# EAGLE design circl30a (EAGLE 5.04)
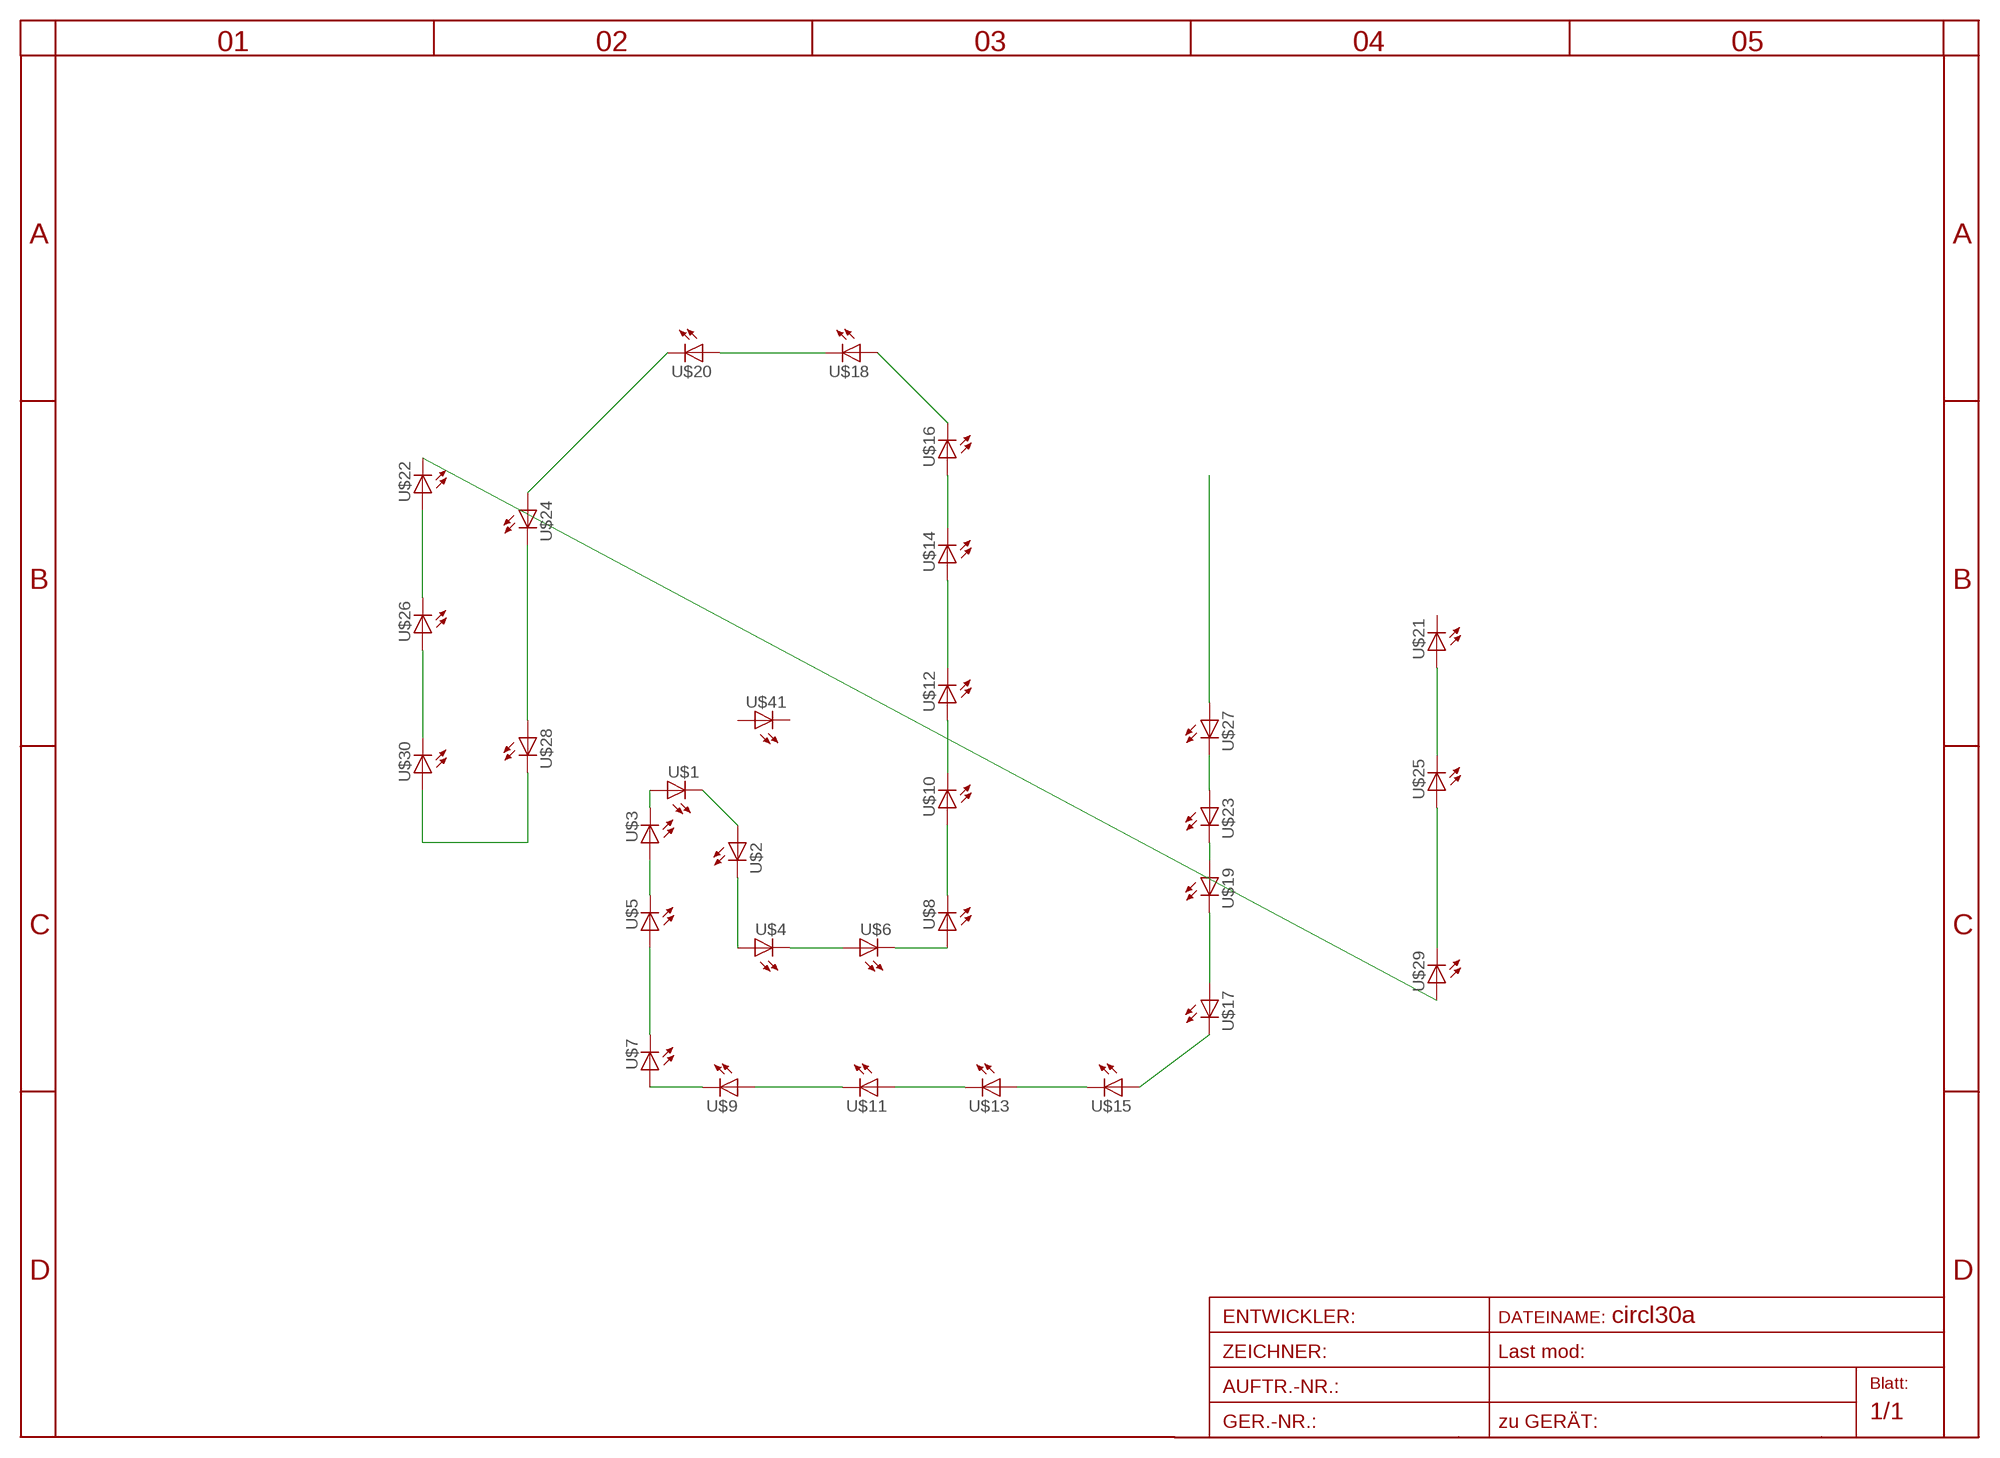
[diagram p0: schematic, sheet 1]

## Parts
U$1  LED5MM  [LED5MM]
U$2  LED5MM  [LED5MM]
U$3  LED5MM  [LED5MM]
U$4  LED5MM  [LED5MM]
U$5  LED5MM  [LED5MM]
U$6  LED5MM  [LED5MM]
U$7  LED5MM  [LED5MM]
U$8  LED5MM  [LED5MM]
U$9  LED5MM  [LED5MM]
U$10  LED5MM  [LED5MM]
U$11  LED5MM  [LED5MM]
U$12  LED5MM  [LED5MM]
U$13  LED5MM  [LED5MM]
U$14  LED5MM  [LED5MM]
U$15  LED5MM  [LED5MM]
U$16  LED5MM  [LED5MM]
U$17  LED5MM  [LED5MM]
U$18  LED5MM  [LED5MM]
U$19  LED5MM  [LED5MM]
U$20  LED5MM  [LED5MM]
U$21  LED5MM  [LED5MM]
U$22  LED5MM  [LED5MM]
U$23  LED5MM  [LED5MM]
U$24  LED5MM  [LED5MM]
U$25  LED5MM  [LED5MM]
U$26  LED5MM  [LED5MM]
U$27  LED5MM  [LED5MM]
U$28  LED5MM  [LED5MM]
U$29  LED5MM  [LED5MM]
U$30  LED5MM  [LED5MM]
U$41  LED5MM  [LED5MM]

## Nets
N$1: U$10.K(C) U$12.A
N$2: U$22.K(C) U$29.A
N$3: U$27.A
N$4: U$20.K(C) U$24.A
N$5: U$24.K(C) U$28.A
N$6: U$12.K(C) U$14.A
N$7: U$14.K(C) U$16.A
N$8: U$16.K(C) U$18.A
N$9: U$18.K(C) U$20.A
N$10: U$22.A U$26.K(C)
N$11: U$8.K(C) U$10.A
N$12: U$6.K(C) U$8.A
N$13: U$4.K(C) U$6.A
N$14: U$2.K(C) U$4.A
N$15: U$1.K(C) U$2.A
N$16: U$1.A U$3.K(C)
N$17: U$3.A U$5.K(C)
N$18: U$5.A U$7.K(C)
N$19: U$7.A U$9.K(C)
N$20: U$9.A U$11.K(C)
N$21: U$11.A U$13.K(C)
N$22: U$13.A U$15.K(C)
N$23: U$15.A U$17.K(C)
N$24: U$17.A U$19.K(C)
N$25: U$25.A U$29.K(C)
N$26: U$21.A U$25.K(C)
N$27: U$26.A U$30.K(C)
N$28: U$23.A U$27.K(C)
N$29: U$19.A U$23.K(C)
N$30: U$28.K(C) U$30.A
Unconnected: U$21.K(C) U$41.A U$41.K(C)

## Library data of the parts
U$1-U$30 U$41 = led(2):LED: LED

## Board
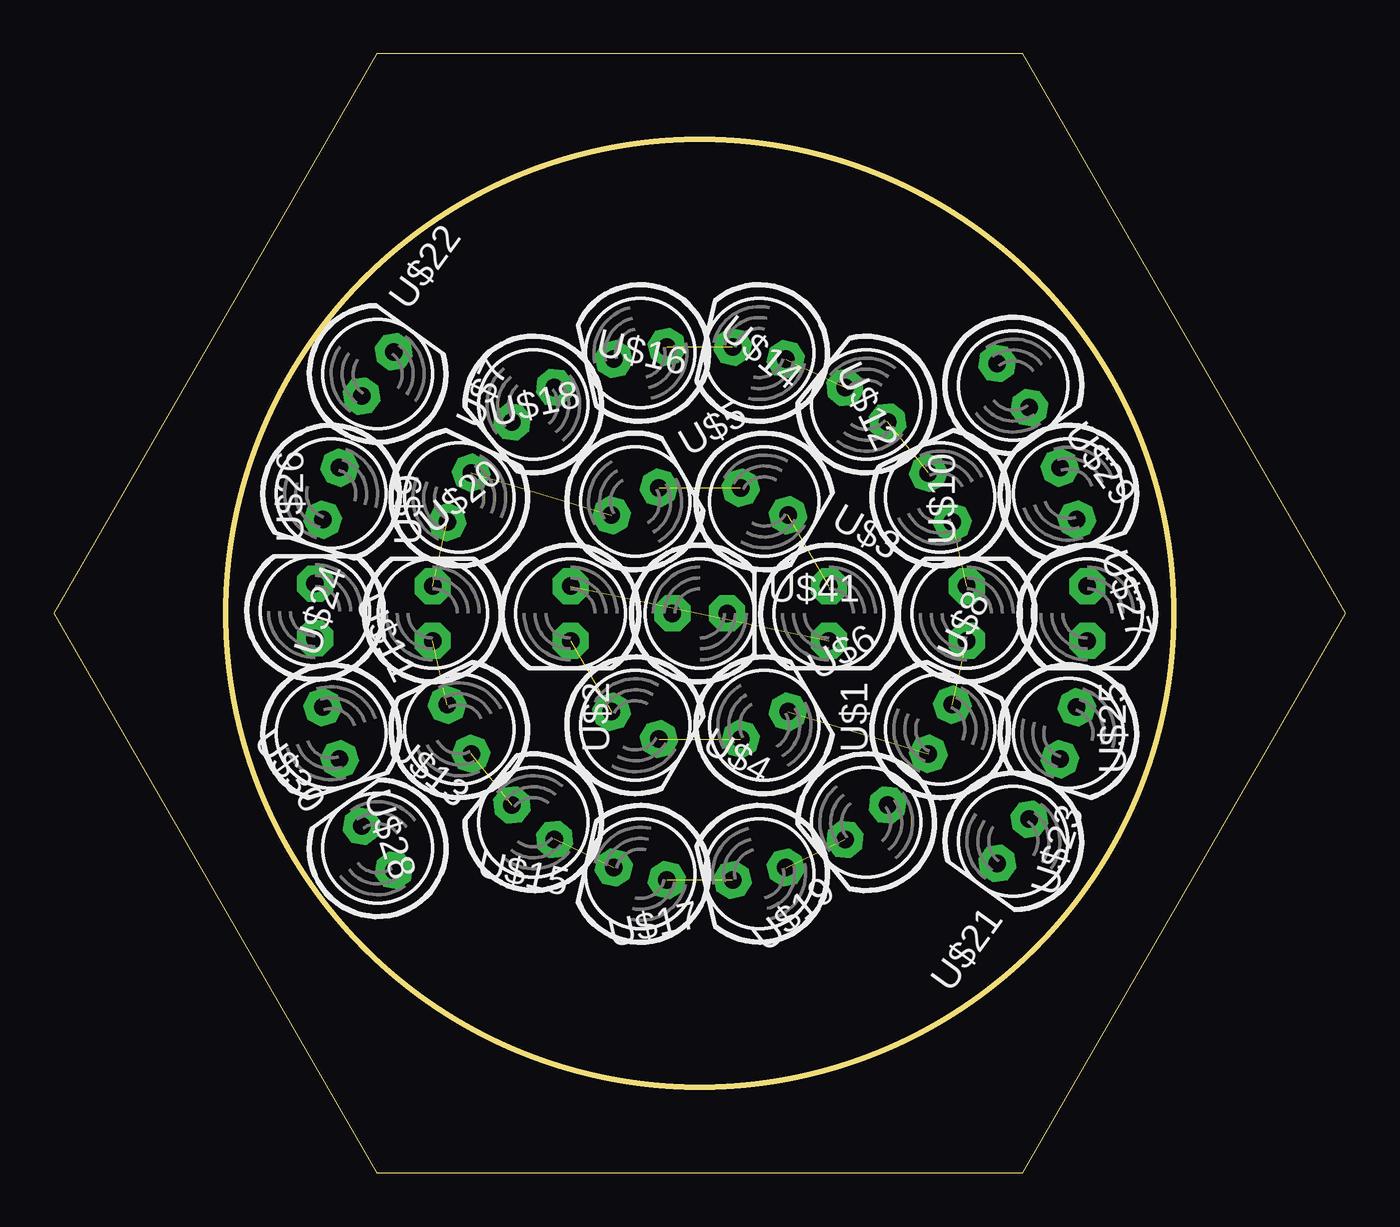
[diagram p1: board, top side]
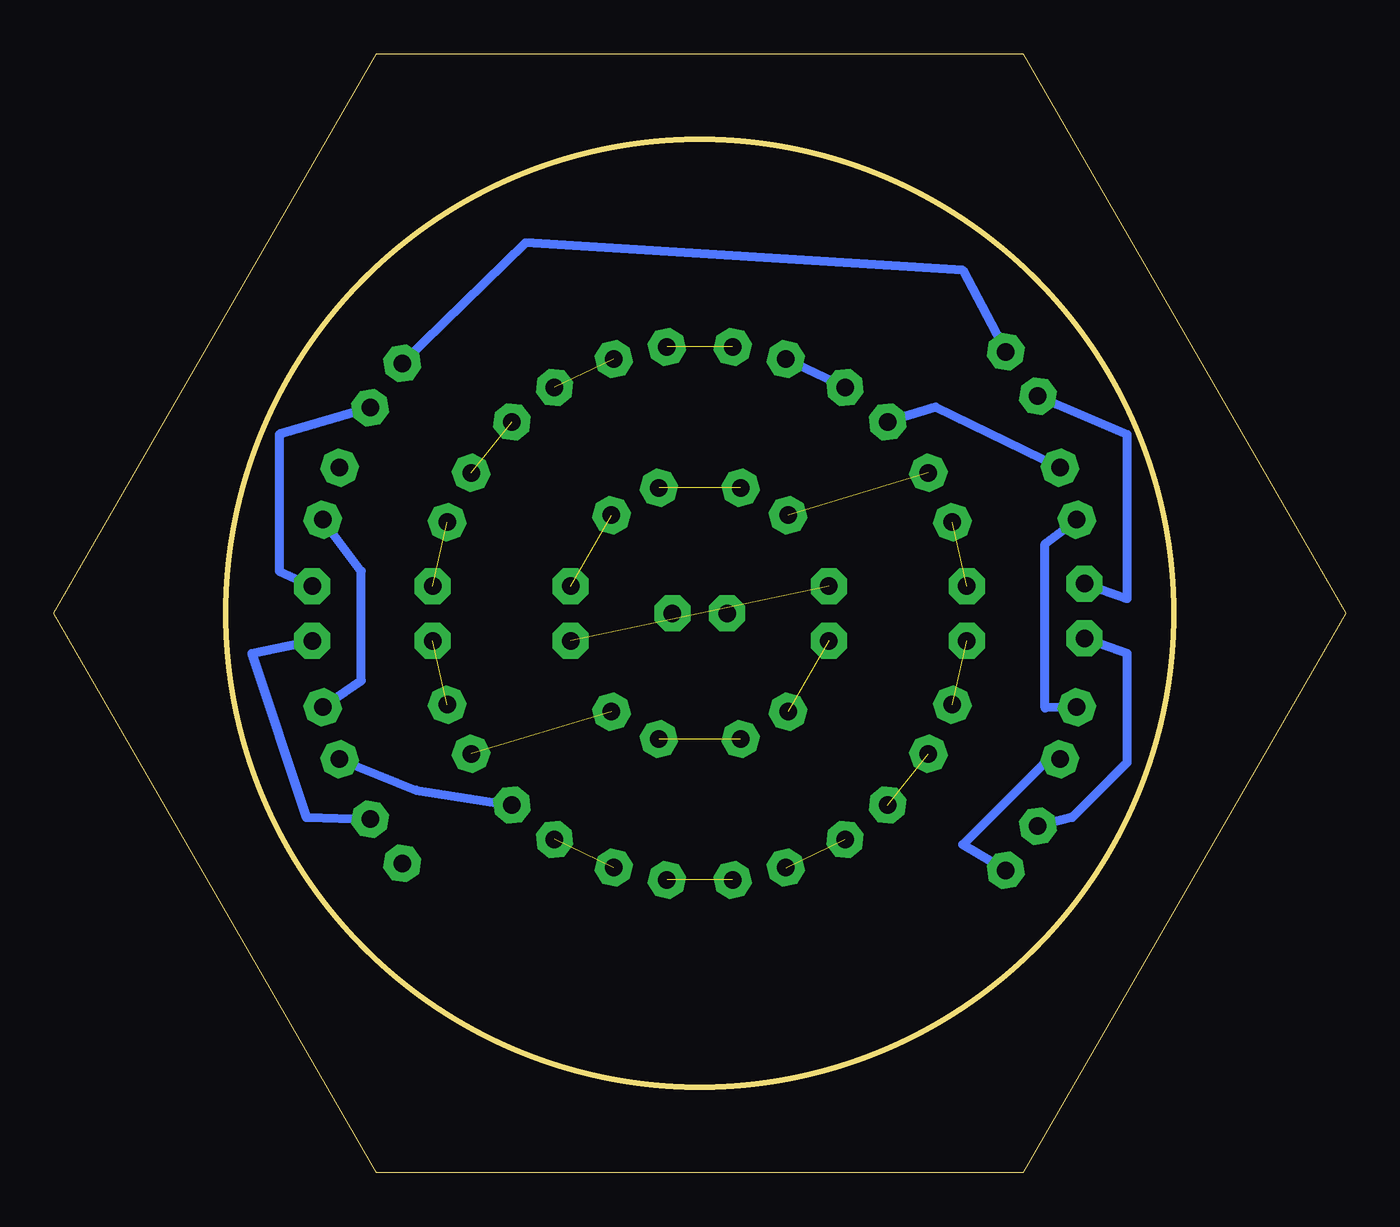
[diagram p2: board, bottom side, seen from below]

Size 60 x 51.96 mm. Coordinates in mm from the lower left corner, seen from the top.
Outline: 15,0 45,0 60,25.98 45,51.96 15,51.96 0,25.98 15,0
Outline: circle at 30,25.98 radius 22
Copper layers (1*16): Top 0.035mm / dielectric 1.5mm / Bottom 0.035mm
Design rules "default": minimum track width 10mil, minimum drill 24mil, track to track 8mil, track to pad 8mil, pad to pad 8mil, via to via 8mil, smd to smd 8mil, copper to edge 40mil, drill to drill 8mil, minimum pad ring 10mil, minimum via ring 8mil, stop-mask expansion 4mil, vias tented up to drill 0mil, thermal gap 10mil

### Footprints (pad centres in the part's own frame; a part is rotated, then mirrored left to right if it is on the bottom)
LED5MM = drill 0.813 pad 1.676 octagon: A -1.27,0; K 1.27,0

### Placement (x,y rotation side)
U$1  36,25.98 270 top
U$2  24,25.98 270 top
U$3  33,31.18 330 top
U$4  27,20.78 330 top
U$5  27,31.18 30 top
U$6  33,20.78 30 top
U$7  18.83,31.36 64 top
U$8  41.17,20.6 64 top
U$9  17.6,25.98 90 top
U$10  42.4,25.98 90 top
U$11  18.83,20.6 116 top
U$12  41.17,31.36 116 top
U$13  22.27,16.29 141 top
U$14  37.73,35.67 141 top
U$15  27.24,13.89 167 top
U$16  32.76,38.07 167 top
U$17  32.76,13.89 193 top
U$18  27.24,38.07 193 top
U$19  37.73,16.29 219 top
U$20  22.27,35.67 219 top
U$21  44.56,15.4 234 top
U$22  15.04,37.1 54 top
U$23  47.12,20.42 252 top
U$24  12.88,31.54 252 top
U$25  48,25.98 270 top
U$26  12.13,26.09 90 top
U$27  47.12,31.54 288 top
U$28  12.88,20.42 288 top
U$29  44.56,36.56 306 top
U$30  15.04,15.08 126 top
U$41  30,25.98 0 top

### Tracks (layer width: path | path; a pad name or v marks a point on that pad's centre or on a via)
N$1  (1 unrouted)
N$2
  Bottom 0.406: U$29.A 38.1,43.18 17.78,41.91 U$22.K
N$4
  Bottom 0.406: U$24.A 19.05,35.56 U$20.K
N$5
  Bottom 0.406: U$28.A 13.97,21.59 13.97,29.21 U$24.K
N$6  (1 unrouted)
N$7  (1 unrouted)
N$8  (1 unrouted)
N$9
  Bottom 0.406: U$20.A U$18.K
N$10
  Bottom 0.406: U$22.A 10.16,34.29 10.16,26.67 U$26.K
N$11  (1 unrouted)
N$12  (1 unrouted)
N$13  (1 unrouted)
N$14  (1 unrouted)
N$15  (1 unrouted)
N$16  (1 unrouted)
N$17  (1 unrouted)
N$18  (1 unrouted)
N$19  (1 unrouted)
N$20  (1 unrouted)
N$21  (1 unrouted)
N$22  (1 unrouted)
N$23  (1 unrouted)
N$24  (1 unrouted)
N$25
  Bottom 0.406: U$29.K 49.53,34.29 49.53,27.94 U$25.A
N$26
  Bottom 0.406: U$25.K 50.8,24.13 48.26,16.51 U$21.A
N$27
  Bottom 0.406: U$26.A 10.16,24.13 10.16,19.05 12.7,16.51 U$30.K
N$28
  Bottom 0.406: U$23.A 45.72,22.86 45.72,27.94 U$27.K
N$29
  Bottom 0.406: U$23.K 43.18,17.78 U$19.A
N$30
  Bottom 0.406: U$30.A 17.78,15.24 13.97,19.05 U$28.K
